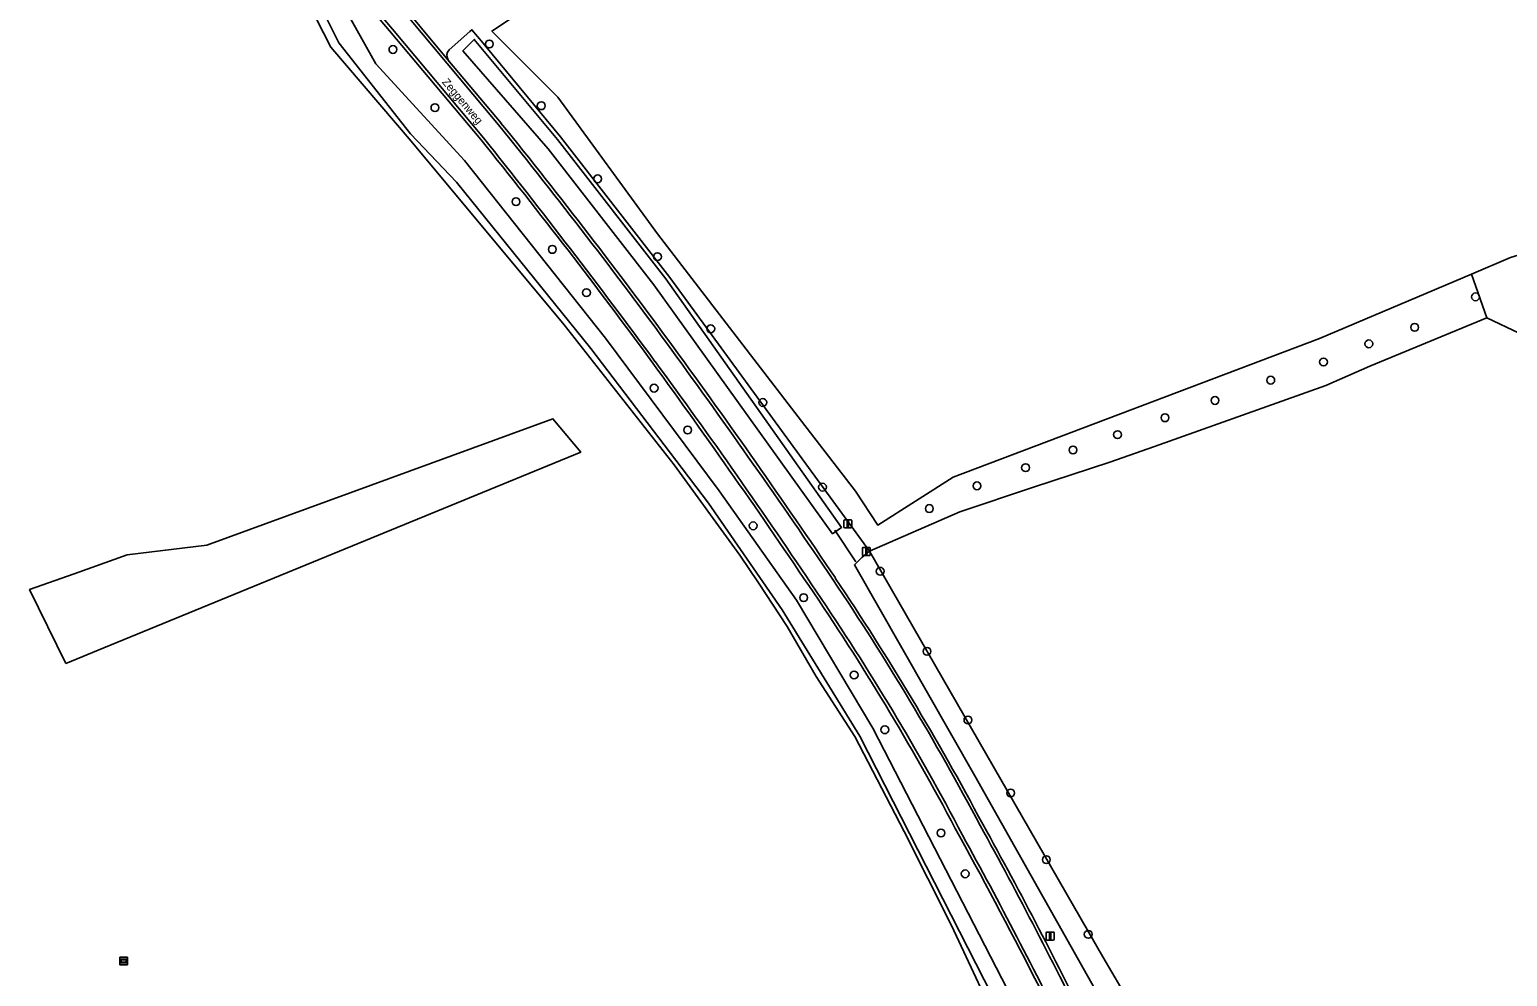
# Model space of a CAD drawing. Extents: x 164494 to 166241, y 382475 to 384495.
# Drawn here: x 165173.5 to 165358.1, y 383258 to 383376.3 of the extents above; entities that cross this region are included whole.
import ezdxf

# ---------------------------------------------------------------- set-up
doc = ezdxf.new("R2010")
doc.units = 0
for name, color, linetype in [('IMGEO_Afsluitpaal', 7, 'Continuous'), ('IMGEO_Boom', 7, 'Continuous'), ('IMGEO_Bouwland', 7, 'Continuous'), ('IMGEO_Duiker', 7, 'Continuous'), ('IMGEO_Grasland_agrarisch', 7, 'Continuous'), ('IMGEO_Grasland_overig', 7, 'Continuous'), ('IMGEO_Greppel_droge_sloot', 7, 'Continuous'), ('IMGEO_Groenvoorziening', 7, 'Continuous'), ('IMGEO_Hek', 7, 'Continuous'), ('IMGEO_Loofbos', 7, 'Continuous'), ('IMGEO_Openbare_ruimte_label', 7, 'Continuous'), ('IMGEO_Rijbaan_lokaal_gesloten', 7, 'Continuous'), ('IMGEO_Rijbaan_lokaal_open', 7, 'Continuous'), ('IMGEO_Verkeersbordpaal', 7, 'Continuous'), ('IMGEO_Verklikker', 7, 'Continuous'), ('IMGEO_Waterloop', 7, 'Continuous')]:
    doc.layers.add(name, color=color, linetype=linetype)

msp = doc.modelspace()

# ---------------------------------------------------------------- linework, layer by layer
at = {"layer": 'IMGEO_Afsluitpaal'}
for p, q in [((165275.21, 383314.11), (165275.21, 383314.91)), ((165275.21, 383314.91), (165275.21, 383314.11)), ((165275.31, 383315.01), (165276.1, 383315.01)), ((165276.1, 383315.01), (165275.31, 383315.01)), ((165276.2, 383314.91), (165276.2, 383314.11)), ((165276.2, 383314.11), (165276.2, 383314.91)), ((165276.1, 383314.01), (165275.31, 383314.01)), ((165275.31, 383314.01), (165276.1, 383314.01)), ((165277.51, 383310.65), (165277.51, 383311.45)), ((165277.51, 383311.45), (165277.51, 383310.65)), ((165277.61, 383311.55), (165278.4, 383311.55)), ((165278.4, 383311.55), (165277.61, 383311.55)), ((165278.4, 383310.55), (165277.61, 383310.55)), ((165277.61, 383310.55), (165278.4, 383310.55)), ((165278.5, 383311.45), (165278.5, 383310.65)), ((165278.5, 383310.65), (165278.5, 383311.45))]:
    msp.add_line(p, q, dxfattribs=at)
for points in [[(165275.63, 383314.88), (165275.78, 383314.88), (165275.78, 383314.13), (165275.63, 383314.13), (165275.63, 383314.88)], [(165277.93, 383311.43), (165278.08, 383311.43), (165278.08, 383310.68), (165277.93, 383310.68), (165277.93, 383311.43)]]:
    msp.add_lwpolyline(points, dxfattribs=at)
for centre, start, end in [((165275.31, 383314.91), 90, 180), ((165275.31, 383314.91), 90, 180), ((165275.31, 383314.11), 180, 270), ((165275.31, 383314.11), 180, 270), ((165276.1, 383314.91), 0, 90), ((165276.1, 383314.91), 360, 90), ((165276.1, 383314.11), 270, 0), ((165276.1, 383314.11), 270, 0), ((165277.61, 383311.45), 90, 180), ((165277.61, 383311.45), 90, 180), ((165277.61, 383310.65), 180, 270), ((165277.61, 383310.65), 180, 270), ((165278.4, 383311.45), 0, 90), ((165278.4, 383311.45), 360, 90), ((165278.4, 383310.65), 270, 0), ((165278.4, 383310.65), 270, 0)]:
    msp.add_arc(centre, 0.1, start, end, dxfattribs=at)
at = {"layer": 'IMGEO_Boom'}
for centre in [(165218.86, 383373.77), (165230.9, 383374.45), (165224.11, 383366.5), (165237.39, 383366.74), (165244.44, 383357.61), (165234.24, 383354.75), (165238.77, 383348.79), (165251.91, 383347.88), (165243.04, 383343.39), (165354.11, 383342.86), (165258.57, 383338.87), (165346.51, 383339.05), (165340.79, 383336.99), (165335.12, 383334.73), (165328.53, 383332.45), (165251.49, 383331.46), (165265.07, 383329.67), (165321.57, 383329.92), (165315.32, 383327.76), (165255.68, 383326.22), (165309.39, 383325.65), (165303.83, 383323.73), (165297.9, 383321.52), (165272.53, 383319.09), (165291.83, 383319.25), (165285.88, 383316.41), (165263.87, 383314.26), (165279.74, 383308.58), (165270.18, 383305.28), (165285.58, 383298.57), (165276.48, 383295.62), (165290.7, 383289.99), (165280.32, 383288.78), (165296.04, 383280.88), (165287.34, 383275.88), (165300.49, 383272.54), (165290.36, 383270.78), (165305.73, 383263.22)]:
    msp.add_circle(centre, 0.489, dxfattribs=at)
at = {"layer": 'IMGEO_Bouwland'}
for points in [[(165252.37, 383390.1), (165231.22, 383376.07), (165239.47, 383367.81), (165251.91, 383350.74), (165269.9, 383327.33), (165276.64, 383318.6), (165279.44, 383314.34), (165288.87, 383320.35), (165334.61, 383337.67), (165353.62, 383345.7), (165358.5, 383347.76), (165369.05, 383350.98), (165371.92, 383351.86), (165400.24, 383356.46), (165486.82, 383373.52), (165482.52, 383418.43)], [(165208.62, 383129.64), (165221.63, 383148.27), (165235.88, 383165.81), (165243.09, 383174.04), (165249.4, 383180.04), (165264.13, 383195.59), (165272.13, 383206.26), (165294.98, 383238.21), (165296.13, 383241.77), (165296.52, 383246.31), (165295.34, 383250), (165288.65, 383264.32), (165282.74, 383276.07), (165276.55, 383287.95), (165271.73, 383295.45), (165268.1, 383301.68), (165264.53, 383307.12), (165262.21, 383310.58), (165254, 383321.87), (165240.26, 383339.36), (165221.15, 383362.32), (165211.1, 383374.04), (165206.52, 383383.04)]]:
    msp.add_lwpolyline(points, dxfattribs=at)
msp.add_lwpolyline([(165177.99, 383297.06), (165173.46, 383306.28), (165179.05, 383308.27), (165185.66, 383310.63), (165195.6, 383311.83), (165238.84, 383327.63), (165242.32, 383323.46), (165182.73, 383299.01)], close=True, dxfattribs=at)
at = {"layer": 'IMGEO_Duiker'}
msp.add_lwpolyline([(165274.08, 383313.73), (165276.71, 383309.74)], dxfattribs=at)
at = {"layer": 'IMGEO_Grasland_agrarisch'}
msp.add_lwpolyline([(165363.62, 383336.4), (165355.52, 383340.26), (165340.91, 383334.22), (165335.42, 383331.79), (165314.02, 383324.18), (165308.42, 383322.2), (165298.89, 383319.1), (165289.68, 383316.01), (165278.41, 383311.09), (165307.56, 383260.41), (165309.81, 383256.58), (165311.26, 383254.46), (165315.92, 383243.68), (165318.8, 383237.01), (165333.36, 383203.27), (165341.96, 383183.02), (165348.3, 383164.9), (165353.33, 383137.38), (165354.79, 383114.23)], dxfattribs=at)
at = {"layer": 'IMGEO_Grasland_overig'}
for points in [[(165229.83, 383362.53), (165218.45, 383376.1), (165187.19, 383412.92)], [(165206.52, 383383.04), (165211.1, 383374.04), (165221.15, 383362.32), (165240.26, 383339.36), (165254, 383321.87), (165262.21, 383310.58), (165264.53, 383307.12), (165268.1, 383301.68), (165271.73, 383295.45), (165276.55, 383287.95), (165282.74, 383276.07), (165288.65, 383264.32), (165295.34, 383250), (165296.52, 383246.31), (165296.13, 383241.77), (165294.98, 383238.21), (165272.13, 383206.26), (165264.13, 383195.59), (165249.4, 383180.04), (165243.09, 383174.04), (165235.88, 383165.81), (165221.63, 383148.27), (165208.62, 383129.64)], [(165210.68, 383382.82), (165216.71, 383371.96), (165227.79, 383359.88), (165245.43, 383337.7), (165259.63, 383318.64), (165269.27, 383304.96), (165278.83, 383288.97), (165297.71, 383252.3), (165298.61, 383250), (165299.55, 383247.59), (165299.56, 383247.19), (165299.71, 383242.77), (165299.29, 383241.73), (165298.1, 383238.79), (165282.4, 383216.51), (165271.84, 383201.86), (165264.61, 383193.36), (165246.45, 383174.39), (165237.82, 383165.67), (165226.93, 383152.39), (165210.82, 383130.6)], [(165295.84, 383251.43), (165277.18, 383287.98), (165267.5, 383303.78), (165258.27, 383317.09), (165254.19, 383322.46), (165243.6, 383336.41), (165226.82, 383357.18), (165221.04, 383363.22), (165212.09, 383374.58), (165208.31, 383382.2)], [(165308.97, 383252.14), (165291.58, 383283.02), (165276.51, 383309.4), (165277.46, 383310.29), (165278.41, 383311.09), (165276.06, 383314.3), (165253.45, 383345.3), (165239.8, 383362.86), (165230.48, 383374.14), (165230.14, 383374.54), (165228.74, 383376.23), (165228.49, 383376.01), (165225.87, 383373.72)], [(165225.74, 383372.48), (165232.37, 383364.58)]]:
    msp.add_lwpolyline(points, dxfattribs=at)
msp.add_lwpolyline([(165238.24, 383361.34), (165227.6, 383373.61), (165229.02, 383375.02), (165239.42, 383362.53), (165252.95, 383345.11), (165274.91, 383314.06), (165273.78, 383313.27), (165251.47, 383344.35)], close=True, dxfattribs=at)
for centre, radius, start, end in [((165226.68, 383373.02), 1.07, 138.9279, 209.7242), ((164660.05, 382902.18), 735.77, 36.17325, 38.93656), ((164598.87, 382854.82), 809.87, 36.32829, 38.82237), ((164527.58, 382805.49), 899.78, 33.93099, 36.1644), ((164492.65, 382781.89), 938.65, 33.93378, 36.07382), ((164976.19, 383108.35), 358.5, 28.057, 33.791), ((165007.15, 383127.06), 319.1, 27.7161, 34.0833), ((164769.72, 382988.17), 594.02, 26.85677, 28.9236), ((164809.49, 383009.58), 552.14, 25.8918, 28.9653)]:
    msp.add_arc(centre, radius, start, end, dxfattribs=at)
at = {"layer": 'IMGEO_Greppel_droge_sloot'}
msp.add_lwpolyline([(165276.51, 383309.4), (165291.58, 383283.02), (165308.97, 383252.14), (165310.18, 383250), (165313.4, 383242.58), (165314.24, 383242.95), (165315.1, 383243.33), (165315.92, 383243.68), (165311.26, 383254.46), (165309.81, 383256.58), (165307.56, 383260.41), (165278.41, 383311.09), (165277.46, 383310.29)], close=True, dxfattribs=at)
at = {"layer": 'IMGEO_Groenvoorziening'}
for points in [[(165353.62, 383345.7), (165334.61, 383337.67), (165288.87, 383320.35), (165279.44, 383314.34), (165276.64, 383318.6), (165269.9, 383327.33), (165251.91, 383350.74), (165239.47, 383367.81), (165231.22, 383376.07), (165252.37, 383390.1), (165268.61, 383398.2), (165271.45, 383399.77), (165285.27, 383405.93), (165295.96, 383410.12), (165303.39, 383414.84), (165307.44, 383418.43), (165310.52, 383422.4), (165311.05, 383423.5), (165311.95, 383425.41), (165309.57, 383424.86), (165309.04, 383426.86), (165307.53, 383423.75), (165306.68, 383422.01)], [(165222.21, 383376.7), (165225.74, 383372.48)], [(165225.87, 383373.72), (165228.49, 383376.01), (165228.74, 383376.23), (165230.14, 383374.54), (165230.48, 383374.14), (165239.8, 383362.86), (165253.45, 383345.3), (165276.06, 383314.3), (165278.41, 383311.09), (165289.68, 383316.01), (165298.89, 383319.1), (165308.42, 383322.2), (165314.02, 383324.18), (165335.42, 383331.79), (165340.91, 383334.22), (165355.52, 383340.26), (165353.62, 383345.7)]]:
    msp.add_lwpolyline(points, dxfattribs=at)
msp.add_arc((165226.68, 383373.02), 1.07, 138.9279, 209.7242, dxfattribs=at)
at = {"layer": 'IMGEO_Hek'}
for points in [[(165228.74, 383376.23), (165230.14, 383374.54)], [(165230.14, 383374.54), (165230.48, 383374.14), (165239.8, 383362.86), (165253.45, 383345.3), (165276.06, 383314.3)], [(165276.06, 383314.3), (165278.41, 383311.09)]]:
    msp.add_lwpolyline(points, dxfattribs=at)
at = {"layer": 'IMGEO_Loofbos'}
for points in [[(165372.77, 383334.46), (165374.41, 383334.8), (165373.91, 383337.75), (165371.52, 383344.68), (165370.77, 383346.57), (165369.38, 383350.06), (165369.05, 383350.98), (165358.5, 383347.76), (165353.62, 383345.7), (165355.52, 383340.26), (165363.62, 383336.4), (165371.97, 383334.46)], [(165177.99, 383297.06), (165182.73, 383299.01), (165242.32, 383323.46), (165238.84, 383327.63), (165195.6, 383311.83), (165185.66, 383310.63), (165179.05, 383308.27), (165173.46, 383306.28)]]:
    msp.add_lwpolyline(points, close=True, dxfattribs=at)
at = {"layer": 'IMGEO_Rijbaan_lokaal_gesloten'}
for points in [[(165232.06, 383364.34), (165220.71, 383377.87), (165189.48, 383414.85)], [(165187.47, 383413.18), (165218.8, 383376.29), (165230.16, 383362.73)]]:
    msp.add_lwpolyline(points, dxfattribs=at)
for centre, radius, start, end in [((164669.04, 382908.85), 724.2, 36.16516, 38.97379), ((164585.16, 382845.62), 826.7, 36.27909, 38.72043), ((164420.8, 382729.93), 1030.19, 34.10267, 36.0515), ((164655.87, 382895.5), 740.19, 33.69207, 36.40476), ((164988.26, 383115.68), 344.04, 27.926, 33.894), ((165015.85, 383131.84), 309.58, 27.6744, 34.257), ((164760.39, 382984.24), 604.49, 26.08134, 28.81837), ((164789.34, 382999.96), 574.07, 25.87623, 28.83217)]:
    msp.add_arc(centre, radius, start, end, dxfattribs=at)
at = {"layer": 'IMGEO_Rijbaan_lokaal_open'}
for points in [[(165189.48, 383414.85), (165220.71, 383377.87), (165232.06, 383364.34)], [(165232.37, 383364.58), (165225.74, 383372.48), (165222.21, 383376.7), (165221.02, 383378.12), (165189.77, 383415.07)], [(165187.19, 383412.92), (165218.45, 383376.1), (165229.83, 383362.53)], [(165230.16, 383362.73), (165218.8, 383376.29), (165187.47, 383413.18)]]:
    msp.add_lwpolyline(points, dxfattribs=at)
for centre, radius, start, end in [((164669.04, 382908.85), 724.2, 36.16516, 38.97379), ((164660.05, 382902.18), 735.77, 36.17325, 38.93656), ((164598.87, 382854.82), 809.87, 36.32829, 38.82237), ((164585.16, 382845.62), 826.7, 36.27909, 38.72043), ((164420.8, 382729.93), 1030.19, 34.10267, 36.0515), ((164527.58, 382805.49), 899.78, 33.93099, 36.1644), ((164492.65, 382781.89), 938.65, 33.93378, 36.07382), ((164655.87, 382895.5), 740.19, 33.69207, 36.40476), ((164988.26, 383115.68), 344.04, 27.926, 33.894), ((164976.19, 383108.35), 358.5, 28.057, 33.791), ((165007.15, 383127.06), 319.1, 27.7161, 34.0833), ((165015.85, 383131.84), 309.58, 27.6744, 34.257), ((164769.72, 382988.17), 594.02, 26.85677, 28.9236), ((164760.39, 382984.24), 604.49, 26.08134, 28.81837), ((164789.34, 382999.96), 574.07, 25.87623, 28.83217), ((164809.49, 383009.58), 552.14, 25.8918, 28.9653)]:
    msp.add_arc(centre, radius, start, end, dxfattribs=at)
at = {"layer": 'IMGEO_Verkeersbordpaal'}
for p, q in [((165300.48, 383262.6), (165300.48, 383263.4)), ((165300.48, 383263.4), (165300.48, 383262.6)), ((165300.58, 383263.5), (165301.37, 383263.5)), ((165301.37, 383263.5), (165300.58, 383263.5)), ((165301.37, 383262.5), (165300.58, 383262.5)), ((165300.58, 383262.5), (165301.37, 383262.5)), ((165301.47, 383263.4), (165301.47, 383262.6)), ((165301.47, 383262.6), (165301.47, 383263.4))]:
    msp.add_line(p, q, dxfattribs=at)
msp.add_lwpolyline([(165300.9, 383263.37), (165301.05, 383263.37), (165301.05, 383262.62), (165300.9, 383262.62), (165300.9, 383263.37)], dxfattribs=at)
for centre, start, end in [((165300.58, 383263.4), 90, 180), ((165300.58, 383263.4), 90, 180), ((165300.58, 383262.6), 180, 270), ((165300.58, 383262.6), 180, 270), ((165301.37, 383263.4), 0, 90), ((165301.37, 383263.4), 360, 90), ((165301.37, 383262.6), 270, 0), ((165301.37, 383262.6), 270, 0)]:
    msp.add_arc(centre, 0.1, start, end, dxfattribs=at)
at = {"layer": 'IMGEO_Verklikker'}
for p, q in [((165184.73, 383259.49), (165184.73, 383260.28)), ((165184.73, 383260.28), (165184.73, 383259.49)), ((165184.83, 383260.38), (165185.62, 383260.38)), ((165185.62, 383260.38), (165184.83, 383260.38)), ((165185.62, 383259.39), (165184.83, 383259.39)), ((165184.83, 383259.39), (165185.62, 383259.39)), ((165185.72, 383260.28), (165185.72, 383259.49)), ((165185.72, 383259.49), (165185.72, 383260.28))]:
    msp.add_line(p, q, dxfattribs=at)
for points in [[(165184.83, 383260.12), (165185.61, 383260.12), (165185.61, 383259.65), (165184.83, 383259.65), (165184.83, 383260.12)], [(165184.89, 383260.05), (165184.89, 383259.72), (165185.55, 383259.72), (165185.55, 383260.05), (165184.89, 383260.05)]]:
    msp.add_lwpolyline(points, dxfattribs=at)
for centre, start, end in [((165184.83, 383260.28), 90, 180), ((165184.83, 383260.28), 90, 180), ((165184.83, 383259.49), 180, 270), ((165184.83, 383259.49), 180, 270), ((165185.62, 383260.28), 0, 90), ((165185.62, 383260.28), 360, 90), ((165185.62, 383259.49), 270, 0), ((165185.62, 383259.49), 270, 0)]:
    msp.add_arc(centre, 0.1, start, end, dxfattribs=at)
at = {"layer": 'IMGEO_Waterloop'}
for points in [[(165210.82, 383130.6), (165226.93, 383152.39), (165237.82, 383165.67), (165246.45, 383174.39), (165264.61, 383193.36), (165271.84, 383201.86), (165282.4, 383216.51), (165298.1, 383238.79), (165299.29, 383241.73), (165299.71, 383242.77), (165299.56, 383247.19), (165299.55, 383247.59), (165298.61, 383250), (165297.71, 383252.3), (165278.83, 383288.97), (165269.27, 383304.96), (165259.63, 383318.64), (165245.43, 383337.7), (165227.79, 383359.88), (165216.71, 383371.96), (165210.68, 383382.82)], [(165208.31, 383382.2), (165212.09, 383374.58), (165221.04, 383363.22), (165226.82, 383357.18), (165243.6, 383336.41), (165254.19, 383322.46), (165258.27, 383317.09), (165267.5, 383303.78), (165277.18, 383287.98), (165295.84, 383251.43)]]:
    msp.add_lwpolyline(points, dxfattribs=at)
msp.add_lwpolyline([(165227.6, 383373.61), (165238.24, 383361.34), (165251.47, 383344.35), (165273.78, 383313.27), (165274.91, 383314.06), (165252.95, 383345.11), (165239.42, 383362.53), (165229.02, 383375.02)], close=True, dxfattribs=at)

# ---------------------------------------------------------------- texts
at = {"layer": 'IMGEO_Openbare_ruimte_label'}
msp.add_text('Zeggenweg', height=1, rotation=310.0917, dxfattribs=at).set_placement((165224.93, 383369.67))

doc.saveas('drawing.dxf')
